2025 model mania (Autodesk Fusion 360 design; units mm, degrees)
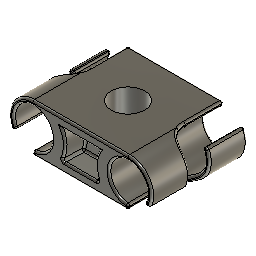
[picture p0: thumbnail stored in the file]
sketch "Sketch1" plane through (0, 0, 0) normal (0, 0, 1) x axis (1, 0, 0)
  line L1 (-10, 110) -> (-160, 110)
  line L2 (-10, 10) -> (-10, 110)
  line L3 (-160, 10) -> (-10, 10)
  line L4 (-160, 110) -> (-160, 10)
  circle C1 centre (-85, 60) radius 17.5
  point P2 (-160, 110)
  point P3 (-10, 110)
  point P5 (-160, 10)
  point P1 (0, 0)
  point P6 (-85, 60)
  horizontal L1
  vertical L2
  horizontal L3
  vertical L4
  dimension "d1" distance P2 P3 = 150
  dimension "d2" distance P2 P5 = 100
  dimension "d3" distance P1 L2 = 10
  dimension "d4" distance P1 L3 = 10
  dimension "d5" diameter C1 = 35
  dimension "d6" distance L2 P6 = 75 (= "d1 / 2")
  dimension "d7" distance L1 P6 = 50 (= "d2 / 2")
extrude "Extrude1" new body sketch "Sketch1" along normal blind 50
work_plane "WorkPlane2"
work_plane "WorkPlane3"
work_axis "WorkAxis3"
fillet "Fillet1" radius 25
sketch "Sketch2" plane through (0, 10, 0) normal (0, -1, 0) x axis (1, 0, 0)
  line L1 (-35, 0) -> (-135, 0)
  line L2 (-135, 50) -> (-35, 50)
  line L3 (-65, 50) -> (-65, 40)
  line L4 (-65, 0) -> (-65, 10)
  line L5 (-105, 50) -> (-105, 40)
  line L6 (-105, 0) -> (-105, 10)
  line L7 (-115, 0) -> (-115, 50)
  line L8 (-55, 0) -> (-55, 50)
  line L9 (-65, 10) -> (-105, 10)
  line L10 (-105, 40) -> (-65, 40)
  arc A1 centre (-135, 25) radius 25 clockwise from (-135, 0) to (-135, 50)
  arc A2 centre (-35, 25) radius 25 clockwise from (-35, 50) to (-35, 0)
  circle C1 centre (-35, 25) radius 20
  circle C2 centre (-135, 25) radius 20
  arc A3 centre (-130.9808, 25) radius 30 clockwise from (-105, 40) to (-105, 10)
  arc A4 centre (-39.0192, 25) radius 30 clockwise from (-65, 10) to (-65, 40)
  point P11 (-65, 50)
  point P13 (-65, 0)
  point P15 (-105, 50)
  point P17 (-105, 0)
  point P18 (-115, 50)
  point P19 (-115, 0)
  point P20 (-55, 50)
  point P21 (-55, 0)
  point P16 (-105, 10)
  point P23 (-105, 10)
  point P12 (-65, 10)
  point P25 (-65, 10)
  point P10 (-65, 40)
  concentric A2 C1
  concentric A1 C2
  coincident L2 P11
  perpendicular L2 L3
  coincident L1 P13
  perpendicular L1 L4
  coincident L2 P15
  perpendicular L2 L5
  coincident L1 P17
  perpendicular L1 L6
  coincident L2 P18
  coincident L1 P19
  perpendicular L1 L7
  tangent C2 L7
  coincident L2 P20
  coincident L1 P21
  perpendicular L1 L8
  tangent C1 L8
  equal L3 L4
  equal L3 L5
  equal L5 L6
  coincident P16 P23
  coincident P12 P25
  dimension "d12" diameter C1 = 40
  dimension "d13" diameter C2 = 40
  dimension "d16" distance L5 L7 = 10
  dimension "d17" distance L6 L7 = 10
  dimension "d18" distance L3 L8 = 10
  dimension "d19" distance L4 L8 = 10
  dimension "d20" distance P10 P11 = 10
  dimension "d21" radius A3 = 30
  dimension "d22" radius A4 = 30
extrude "Extrude2" cut sketch "Sketch2" profile of C1 C2 against normal blind 100
extrude "Extrude3" cut sketch "Sketch2" profile of A3 A4 L9 L10 against normal blind 20 taper -5
sketch "Sketch3" plane through (0, 110, 0) normal (0, 1, 0) x axis (-1, 0, 0)
  line L1 (35, 50) -> (135, 50)
  line L2 (135, 0) -> (35, 0)
  line L3 (105, 40) -> (65, 40)
  line L4 (65, 10) -> (105, 10)
  circle C1 centre (135, 25) radius 20
  circle C2 centre (35, 25) radius 20
  arc A1 centre (135, 25) radius 25 clockwise from (135, 50) to (135, 0)
  arc A2 centre (35, 25) radius 25 clockwise from (35, 0) to (35, 50)
  arc A3 centre (39.0192, 25) radius 30 clockwise from (65, 40) to (65, 10)
  arc A4 centre (130.9808, 25) radius 30 clockwise from (105, 10) to (105, 40)
extrude "Extrude4" cut sketch "Sketch3" profile of A3 L3 A4 L4 against normal blind 20 taper -5
fillet "Fillet2" radius 2 2
sketch "Sketch4" plane through (0, 10, 0) normal (0, -1, 0) x axis (1, 0, 0)
  curve K1 (-64.84, 13.7444) -> (-65.0612, 10.1066)
  curve K2 (-65.0612, 10.1066) -> (-65.127, 10)
  curve K3 (-65.127, 10) -> (-68.4928, 8.1673)
  line L1 (-101.5072, 8.1673) -> (-68.4928, 8.1673)
  curve K4 (-101.5072, 8.1673) -> (-104.873, 10)
  curve K5 (-104.873, 10) -> (-104.9388, 10.1066)
  curve K6 (-104.9388, 10.1066) -> (-105.16, 13.7444)
  line L2 (-61.6038, 41.8327) -> (-108.3962, 41.8327)
  line L3 (-35, 2) -> (-135, 2)
  line L4 (-135, 48) -> (-35, 48)
  line L5 (-35, 0) -> (-35, 25)
  line L6 (-13.3494, 12.5) -> (-35, 25)
  line L7 (-35, 0) -> (-35, 2)
  line L8 (-35, 48) -> (-35, 50)
  line L9 (-156.6506, 12.5) -> (-135, 25)
  line L10 (-135, 0) -> (-135, 25)
  circle C1 centre (-135, 25) radius 22
  arc A1 centre (-130.9808, 25) radius 28.1673 clockwise from (-108.3962, 41.8327) to (-105.16, 13.7444)
  arc A2 centre (-39.0192, 25) radius 28.1673 clockwise from (-64.84, 13.7444) to (-61.6038, 41.8327)
  arc A3 centre (-35, 25) radius 23 clockwise from (-35, 48) to (-35, 2)
  arc A4 centre (-135, 25) radius 23 clockwise from (-135, 2) to (-135, 48)
  circle C2 centre (-35, 25) radius 22
  arc A5 centre (-35, 25) radius 25 clockwise from (-13.3494, 12.5) to (-35, 0)
  arc A6 centre (-35, 25) radius 25 clockwise from (-35, 50) to (-35, 0)
  arc A7 centre (-35, 25) radius 23 clockwise from (-35, 48) to (-35, 2)
  arc A8 centre (-135, 25) radius 25 clockwise from (-135, 0) to (-135, 50)
  arc A9 centre (-135, 25) radius 25 clockwise from (-135, 0) to (-156.6506, 12.5)
  point P18 (-35, 25)
  point P20 (-35, 25)
  point P21 (-35, 0)
  point P24 (-35, 0)
  point P29 (-135, 0)
  point P33 (-135, 0)
  point P2 (-135, 25)
  point P31 (-135, 25)
  coincident P18 P20
  coincident P21 A6
  coincident P21 P24
  coincident P29 P33
  coincident P2 P31
  dimension "d33" angle L5 L6 = 60
  dimension "d36" angle L9 L10 = 60
extrude "Extrude5" cut sketch "Sketch4" profile of C1 A3 A4 C2 A5 L5 L6 L7 A6 A7 A8 A9 L9 L10 against normal blind 40
work_axis "WorkAxis1"
work_axis "WorkAxis2"
work_plane "WorkPlane1" RotateAngle 0
sketch "Sketch7" plane through (0, 110, 0) normal (0, 1, 0) x axis (-1, 0, 0)
  line L1 (68.4928, 8.1673) -> (101.5072, 8.1673)
  curve K1 (68.4928, 8.1673) -> (65.127, 10)
  curve K2 (65.127, 10) -> (65.0612, 10.1066)
  curve K3 (64.84, 36.2556) -> (65.0612, 39.8934)
  curve K4 (65.0612, 39.8934) -> (65.127, 40)
  line L2 (101.5072, 41.8327) -> (68.4928, 41.8327)
  curve K5 (101.5072, 41.8327) -> (104.873, 40)
  curve K6 (104.873, 40) -> (104.9388, 39.8934)
  curve K7 (104.873, 10) -> (101.5072, 8.1673)
  line L3 (35, 48) -> (135, 48)
  line L4 (135, 2) -> (35, 2)
  line L5 (35, 50) -> (35, 25)
  line L6 (13.3494, 37.5) -> (35, 25)
  line L7 (156.6506, 37.5) -> (135, 25)
  line L8 (135, 50) -> (135, 25)
  curve K8 (65.0612, 10.1066) -> (64.84, 13.7444)
  curve K9 (65.127, 40) -> (68.4928, 41.8327)
  curve K10 (104.9388, 39.8934) -> (105.16, 36.2556)
  curve K11 (105.16, 13.7444) -> (104.9388, 10.1066)
  curve K12 (104.9388, 10.1066) -> (104.873, 10)
  arc A1 centre (39.0192, 25) radius 28.1673 clockwise from (64.84, 36.2556) to (64.84, 13.7444)
  arc A2 centre (130.9808, 25) radius 28.1673 clockwise from (105.16, 13.7444) to (105.16, 36.2556)
  circle C1 centre (35, 25) radius 22
  circle C2 centre (135, 25) radius 22
  arc A3 centre (135, 25) radius 23 clockwise from (135, 48) to (135, 2)
  arc A4 centre (35, 25) radius 23 clockwise from (35, 2) to (35, 48)
  arc A5 centre (35, 25) radius 25 clockwise from (13.3494, 37.5) to (35, 50)
  arc A6 centre (35, 25) radius 25 clockwise from (35, 0) to (35, 50)
  arc A7 centre (135, 25) radius 25 clockwise from (135, 50) to (135, 0)
  arc A8 centre (135, 25) radius 25 clockwise from (135, 50) to (156.6506, 37.5)
  point P19 (35, 25)
  point P25 (35, 25)
  point P26 (35, 50)
  point P28 (35, 50)
  point P32 (135, 50)
  point P36 (135, 50)
  point P33 (135, 25)
  point P34 (135, 25)
  coincident P19 P25
  coincident P26 P28
  coincident P32 P36
  coincident P33 P34
  dimension "d43" angle L5 L6 = 60
  dimension "d44" angle L7 L8 = 60
extrude "Extrude6" cut sketch "Sketch7" profile of C1 C2 A3 A4 A5 L5 L6 A6 A7 A8 L7 L8 against normal blind 40
sketch "Sketch6" plane through (0, 0, 25) normal (0, 0, 1) x axis (1, 0, 0)
  line L1 (-17.6795, 108) -> (-17.6795, 70)
  line L2 (-15, 108) -> (-55, 108)
  line L3 (-35, 70) -> (-35, 108)
  line L4 (-35, 70) -> (-17.6795, 70)
  line L5 (-17.6795, 12) -> (-17.6795, 50)
  line L6 (-55, 12) -> (-15, 12)
  line L7 (-35, 50) -> (-35, 12)
  line L8 (-17.6795, 50) -> (-35, 50)
  line L9 (-135, 108) -> (-135, 70)
  line L10 (-115, 108) -> (-155, 108)
  line L11 (-152.3205, 70) -> (-152.3205, 108)
  line L12 (-152.3205, 70) -> (-135, 70)
  line L13 (-135, 12) -> (-135, 50)
  line L14 (-155, 12) -> (-115, 12)
  line L15 (-152.3205, 50) -> (-152.3205, 12)
  line L16 (-135, 50) -> (-152.3205, 50)
  line L17 (-113, 10) -> (-157, 10)
  line L18 (-13, 10) -> (-57, 10)
  line L19 (-10, 12) -> (-15, 12)
  line L20 (-10, 10) -> (-10, 12)
  line L21 (-10, 50) -> (-10, 10)
  line L22 (-10, 70) -> (-35, 70)
  line L23 (-10, 50) -> (-10, 70)
  line L24 (-160, 10) -> (-157, 10)
  line L25 (-160, 50) -> (-160, 10)
  line L26 (-160, 70) -> (-160, 50)
  line L27 (-152.3205, 70) -> (-160, 70)
  arc A1 centre (-15.0102, 69.3623) radius 20 clockwise from (-10, 50) to (-35, 70)
  arc A2 centre (-154.9898, 69.3623) radius 20 clockwise from (-135, 70) to (-160, 50)
  point P9 (-15, 12)
  point P26 (-15, 12)
  point P7 (-35, 70)
  point P35 (-35, 70)
  point P29 (-10, 50)
  point P36 (-10, 50)
  point P37 (-35, 70)
  point P22 (-157, 10)
  point P39 (-157, 10)
  point P12 (-135, 70)
  point P43 (-135, 70)
  point P17 (-152.3205, 70)
  point P45 (-152.3205, 70)
  point P28 (-10, 10)
  point P38 (-10, 70)
  point P25 (-13, 10)
  point P40 (-160, 10)
  point P41 (-160, 50)
  point P44 (-160, 70)
  coincident P9 P26
  parallel L6 L19
  perpendicular L19 L20
  vertical L21
  coincident P7 P35
  coincident P29 P36
  coincident P7 P37
  perpendicular L3 L22
  horizontal L24
  coincident P22 P39
  vertical L25
  coincident P12 P43
  vertical L26
  coincident P17 P45
  dimension "d49" distance P28 P29 = 40
  dimension "d50" radius A1 = 20
  dimension "d51" distance P29 P38 = 20
  dimension "d52" distance P25 P28 = 3
  dimension "d53" angle L21 L23 = 180
  dimension "d56" distance P39 P40 = 3
  dimension "d57" distance P40 P41 = 40
  dimension "d58" radius A2 = 20
  dimension "d59" distance P41 P44 = 20
extrude "Extrude7" cut sketch "Sketch6" profile of L12 A1 L22 L23 A2 L26 L27 along normal blind 50 and against normal blind 13
sketch "Sketch9" plane through (0, 0, 25) normal (0, 0, 1) x axis (1, 0, 0)
  line L1 (-135, 12) -> (-135, 50)
  line L2 (-155, 12) -> (-115, 12)
  line L3 (-152.3205, 49.5412) -> (-152.3205, 12)
  line L4 (-135, 50) -> (-150.1987, 50)
  line L5 (-150.1987, 70) -> (-155, 70)
  line L6 (-150.1987, 50) -> (-150.1987, 70)
  curve K1 (-135, 70) -> (-152.3205, 49.5412)
  line L7 (-135, 108) -> (-135, 70)
  line L8 (-115, 108) -> (-155, 108)
  line L9 (-152.3205, 70) -> (-152.3205, 108)
  line L10 (-157, 110) -> (-113, 110)
  line L11 (-57, 110) -> (-13, 110)
  line L12 (-17.6795, 12) -> (-17.6795, 49.5412)
  line L13 (-55, 12) -> (-15, 12)
  line L14 (-35, 50) -> (-35, 12)
  line L15 (-19.8013, 50) -> (-35, 50)
  curve K2 (-17.6795, 49.5412) -> (-35, 70)
  line L16 (-19.8013, 70) -> (-19.8013, 50)
  line L17 (-15, 70) -> (-19.8013, 70)
  line L18 (-17.6795, 108) -> (-17.6795, 70)
  line L19 (-15, 108) -> (-55, 108)
  line L20 (-35, 70) -> (-35, 108)
  line L21 (-160, 110) -> (-157, 110)
  line L22 (-160, 70) -> (-160, 110)
  line L23 (-160, 50) -> (-160, 70)
  line L24 (-150.1987, 50) -> (-160, 50)
  line L25 (-10, 110) -> (-13, 110)
  line L26 (-10, 70) -> (-10, 110)
  line L27 (-10, 50) -> (-10, 70)
  line L28 (-17.6795, 49.5412) -> (-10, 50)
  line L29 (-10, 50) -> (-19.8013, 50)
  arc A1 centre (-154.9898, 50.6377) radius 20 clockwise from (-160, 70) to (-135, 50)
  arc A2 centre (-15.0102, 50.6377) radius 20 clockwise from (-35, 50) to (-10, 70)
  point P2 (-135, 50)
  point P35 (-135, 50)
  point P17 (-157, 110)
  point P37 (-157, 110)
  point P36 (-160, 70)
  point P39 (-160, 70)
  point P7 (-150.1987, 50)
  point P41 (-150.1987, 50)
  point P18 (-13, 110)
  point P42 (-13, 110)
  point P25 (-35, 50)
  point P47 (-35, 50)
  point P44 (-10, 70)
  point P46 (-10, 70)
  point P20 (-17.6795, 49.5412)
  point P49 (-17.6795, 49.5412)
  point P27 (-19.8013, 50)
  point P55 (-19.8013, 50)
  point P38 (-160, 110)
  point P43 (-10, 110)
  point P48 (-10, 50)
  coincident P2 P35
  coincident P17 P37
  parallel L10 L21
  coincident P36 P39
  parallel L22 L23
  coincident P7 P41
  coincident P18 P42
  parallel L11 L25
  coincident P25 P47
  coincident P44 P46
  vertical L27
  coincident P20 P49
  coincident P27 P55
  dimension "d60" radius A1 = 20
  dimension "d61" angle L21 L22 = 90
  dimension "d62" distance P38 P39 = 40
  dimension "d63" angle L25 L26 = 90
  dimension "d64" distance P43 P44 = 40
  dimension "d65" radius A2 = 20
  dimension "d66" distance P44 P48 = 20
extrude "Extrude8" cut sketch "Sketch9" profile of L4 L5 L6 L9 L15 L16 L17 L18 A1 L23 L24 A2 L27 L29 against normal blind 25 and along normal blind 13
fillet "Fillet3" radius 2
